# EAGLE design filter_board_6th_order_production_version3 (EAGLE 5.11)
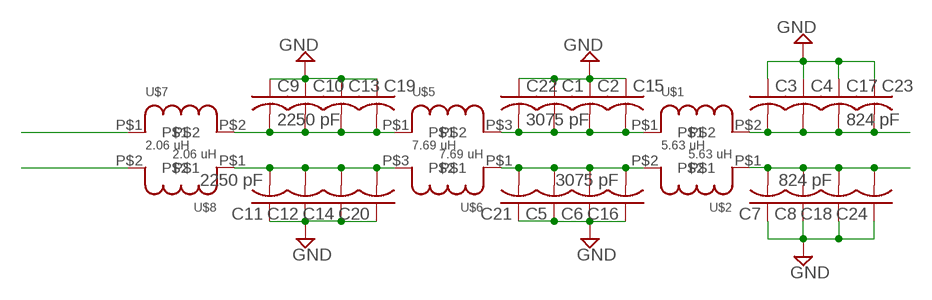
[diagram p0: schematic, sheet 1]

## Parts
C1  C-USC1210  [C1210]
C2  C-USC1210  [C1210]
C3  C-USC1210  [C1210]
C4  C-USC1210  [C1210]
C5  C-USC1210  [C1210]
C6  C-USC1210  [C1210]
C7  C-USC1210  [C1210]
C8  C-USC1210  [C1210]
C9  2250 pF  C-USC1210  [C1210]
C10  C-USC1210  [C1210]
C11  2250 pF  C-USC1210  [C1210]
C12  C-USC1210  [C1210]
C13  C-USC1210  [C1210]
C14  C-USC1210  [C1210]
C15  C-USC1210  [C1210]
C16  3075 pF  C-USC1210  [C1210]
C17  824 pF  C-USC1210  [C1210]
C18  824 pF  C-USC1210  [C1210]
C19  C-USC1210  [C1210]
C20  C-USC1210  [C1210]
C21  C-USC1210  [C1210]
C22  3075 pF  C-USC1210  [C1210]
C23  C-USC1210  [C1210]
C24  C-USC1210  [C1210]
U$1  5.63 uH  IHLP-3232DZ-11  [IHLP-3232DZ]
U$2  5.63 uH  IHLP-3232DZ-11  [IHLP-3232DZ]
U$5  7.69 uH  CDEP147  [SMD_CDEP147]
U$6  7.69 uH  CDEP147  [SMD_CDEP147]
U$7  2.06 uH  NR10050  [SMD_10050]
U$8  2.06 uH  NR10050  [SMD_10050]

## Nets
GND: C1.1 C2.1 C3.1 C4.1 C5.1 C6.1 C7.1 C8.1 C9.1 C10.1 C11.1 C12.1 C13.1 C14.1 C15.1 C16.1 C17.1 C18.1 C19.1 C20.1 C21.1 C22.1 C23.1 C24.1
N$1: C1.2 C2.2 C15.2 C22.2 U$1.P$1 U$5.P$3
N$2: C9.2 C10.2 C13.2 C19.2 U$5.P$1 U$7.P$2
N$3: C7.2 C8.2 C18.2 C24.2 U$2.P$1
N$4: C5.2 C6.2 C16.2 C21.2 U$2.P$2 U$6.P$1
N$5: C11.2 C12.2 C14.2 C20.2 U$6.P$3 U$8.P$1
N$6: U$7.P$1
N$7: C3.2 C4.2 C17.2 C23.2 U$1.P$2
N$9: U$8.P$2

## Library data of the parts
C1-C24 = rcl:C-US: CAPACITOR, American symbol
U$1 U$2 = Cris:IHLP-3232DZ-11: Low Profile, High Current IHLP Inductor
U$5 U$6 = Cris:CDEP147
U$7 U$8 = Cris:NR10050

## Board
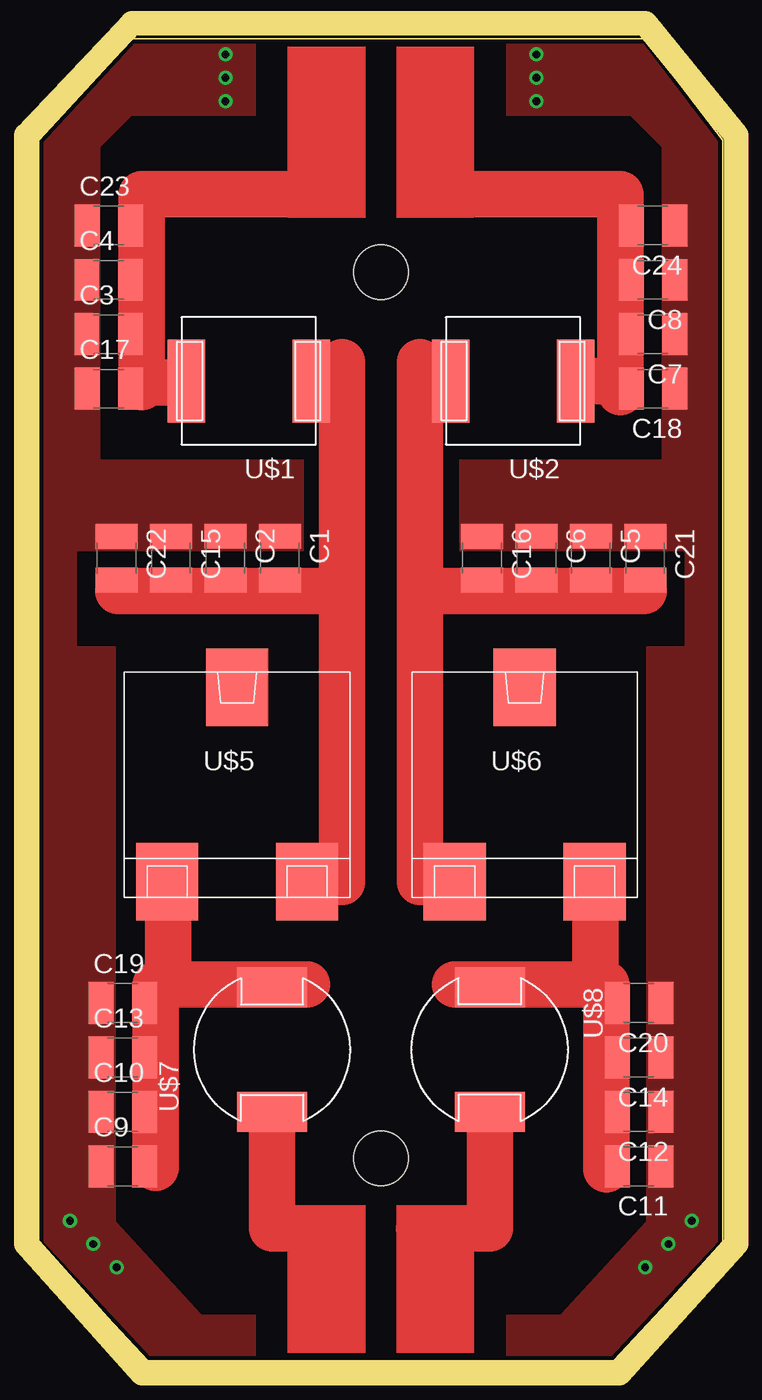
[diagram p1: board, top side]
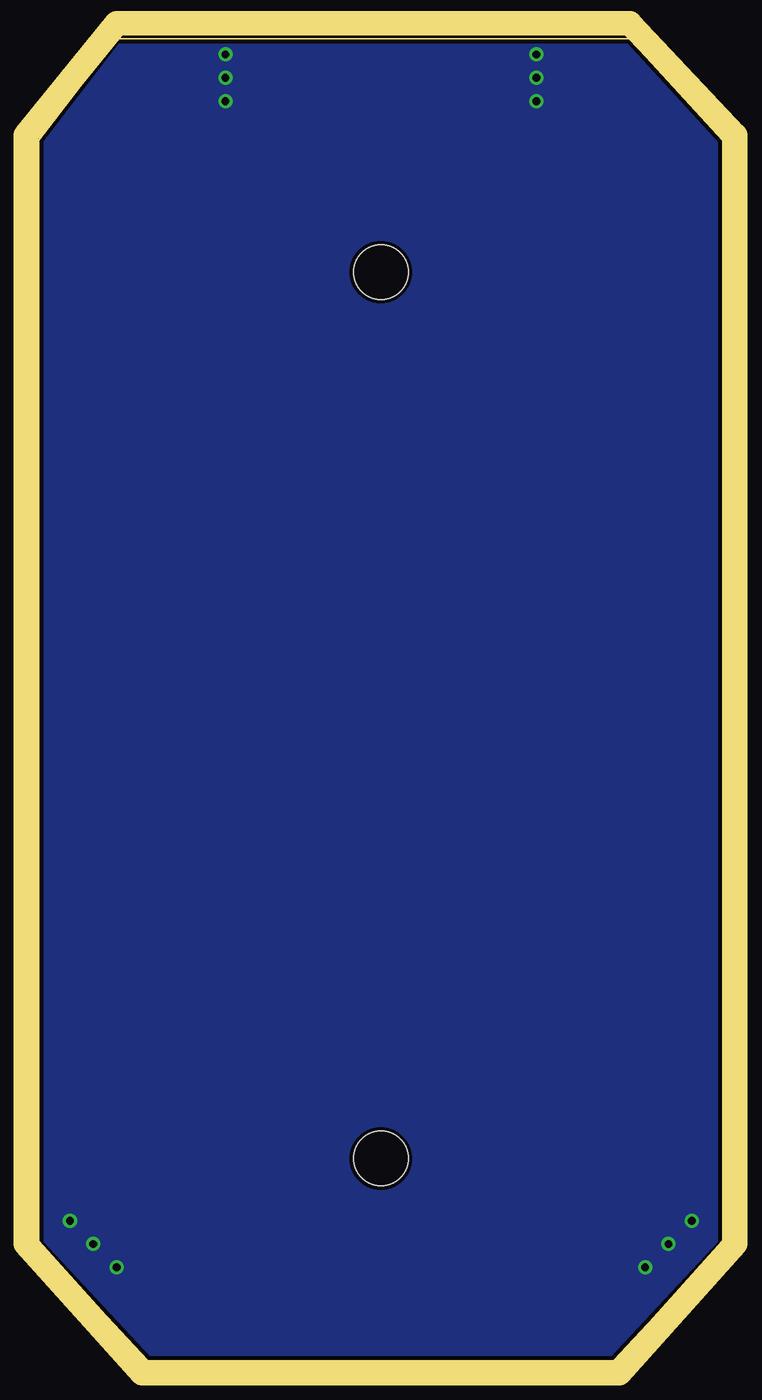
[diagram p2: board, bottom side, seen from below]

Size 44 x 85 mm. Coordinates in mm from the lower left corner, seen from the top.
Outline: 0,7.5 0,78.5 6,85 39,85 44,78.5 44,7.5 37,0 7,0 0,7.5
Copper layers (1*16): Top 0.0711mm / dielectric 1.5mm / Bottom 0.0711mm
Design rules "default *": minimum track width 10mil, minimum drill 24mil, track to track 8mil, track to pad 8mil, pad to pad 8mil, via to via 8mil, smd to smd 8mil, copper to edge 10mil, drill to drill 8mil, minimum pad ring 10mil, minimum via ring 8mil, stop-mask expansion 4mil, vias tented up to drill 0mil, thermal gap 10mil
Holes 3.5 mm at 22,70 22,13
tRestrict: 28 lines
Milling: 8 lines

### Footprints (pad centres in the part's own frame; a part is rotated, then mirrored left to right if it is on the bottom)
C1210 = smd 1.6 x 2.7: 1 -1.4,0; 2 1.4,0
IHLP-3232DZ = smd 2.413 x 5.334: P$1 -4.019,0; P$2 4.019,0
SMD_CDEP147 = smd 5 x 4: P$1 13.5,2.75; P$2 1,7.25; P$3 13.5,11.75
SMD_10050 = smd 2.6 x 4.5: P$1 -4,0; P$2 4,0

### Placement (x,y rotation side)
C1  15.5,51.61 270 top
C2  12,51.61 270 top
C3  4.49,66 0 top
C4  4.49,69.5 0 top
C5  35.5,51.61 270 top
C6  32,51.61 270 top
C7  39.51,66 180 top
C8  39.51,69.5 180 top
C9  5.4,12.5 0 top
C10  5.4,16 0 top
C11  38.6,12.5 180 top
C12  38.6,16 180 top
C13  5.4,19.5 0 top
C14  38.6,19.5 180 top
C15  8.5,51.6 270 top
C16  28.5,51.6 270 top
C17  4.5,62.5 0 top
C18  39.5,62.5 180 top
C19  5.4,23 0 top
C20  38.6,23 180 top
C21  39,51.6 270 top
C22  5,51.6 270 top
C23  4.5,73 0 top
C24  39.5,73 180 top
U$1  13.5,63 180 top
U$2  30.5,63 180 top
U$5  5.5,44.3 270 top
U$6  24,44.3 270 top
U$7  15,20 90 top
U$8  29,20 270 top

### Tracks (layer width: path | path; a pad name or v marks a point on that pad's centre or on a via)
GND  (via drill 0.5)
  other vias: 12,84 12,82.5 12,81 32,84 32,82.5 32,81 2,9 3.5,7.5 5,6 42,9 40.5,7.5 39,6
  pour Top (no thermals): -1,86 45,86 45,-1 -1,-1
  pour Bottom: -1,-1 45,-1 45,86 -1,86
N$1
  Top 1: 19.5,64.2 18.12,64.2 U$1.P$1 | C1.2 C2.2 10,50.05 C15.2 4.9,49.1 5.1,49.5 5.1,50.2 C22.2
  Top 3: 19.5,49.5 5.1,49.5 | 19.5,49.5 19.5,64.2 | 19.5,49.5 19.5,30.8 U$5.P$3
N$2
  Top 1: 7.5,12.4 6.95,12.4 C9.2 C10.2 | C13.2 7.5,22.5 7.5,22.4 | C19.2 7.5,23 7.5,22.9
  Top 2: 15,24.2 U$7.P$2
  Top 3: 8.3,24.2 7.5,24.2 7.5,22.9 7.5,22.4 7.5,12.4 | 8.3,24.2 15,24.2 17.25,24.2 | U$5.P$1 8.3,30.8 8.3,24.2
N$3
  Top 1: U$2.P$1 35.4,63 | 37.4,62.3 37.95,62.3 C18.2 | 37.4,63 38.06,65.5 C7.2 | 37.4,72.7 38.06,72.7 | 38.06,72.7 C8.2 | 37.3,75 37.3,76 | C24.2 38.06,73 38.06,72.7
  Top 3: 35.4,63 37.4,63 | 37.4,63 37.4,72.7 37.4,75 37.3,75 24.52,75 | 37.4,63 37.4,62.3
N$4
  Top 1: 24.5,64.2 25.88,64.2 U$2.P$2 | C16.2 34,50.05 C6.2 C5.2 38.9,49.5 39,49.5 C21.2
  Top 3: 24.5,49.5 38.9,49.5 | 24.5,49.5 24.5,64.2 | 24.5,49.5 24.5,30.8 U$6.P$1
N$5
  Top 1: 29,24.2 U$8.P$1 29.5,24.2 | 36.5,12.3 37.05,12.3 C11.2 C12.2 C14.2 | C20.2 36.5,23 36.5,23.8
  Top 3: 35.8,24.2 36.5,24.2 36.5,23.8 36.5,12.3 | 35.8,24.2 29.5,24.2 29,24.2 26.75,24.2 | U$6.P$3 35.8,30.8 35.8,24.2
N$6
  Top 2: 15,15.3 U$7.P$1
  Top 3: 19.38,8.5 15,8.5 15,15.3
N$7
  Top 1: U$1.P$2 9.88,62.9 8.6,62.9 | 6.6,75 6.6,76 6.5,76 | 6.6,65.8 5.94,65.8 C3.2 C4.2 C23.2 | C17.2 5.95,62.3 6.6,62.6
  Top 3: 6.6,62.9 8.6,62.9 | 6.6,62.6 6.6,62.9 | 6.6,62.9 6.6,65.8 6.6,75 19.44,75
N$9
  Top 1: 29,15.5 U$8.P$2
  Top 2: 24.46,8.5 24.66,8.5
  Top 3: 24.46,8.5 29,8.5 29,15.5
(copper drawn outside any net)
  shapes: Top area x4

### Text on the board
tValues: OUT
